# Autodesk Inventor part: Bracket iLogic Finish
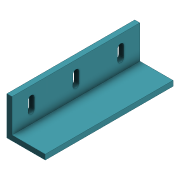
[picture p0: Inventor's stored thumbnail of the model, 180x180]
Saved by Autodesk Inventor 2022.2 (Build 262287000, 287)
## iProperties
RuleStatus: InUse
Created: 2021-08
Part Number: Bracket iLogic Finish
Material: アルミニウム 6061
Document SubType Name: Modeling
Designer: taeku
Density: 2.7 g/cm^3
Appearance: くすんだ青
Author: taeku
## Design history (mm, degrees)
sketch "スケッチ1"
  geometry: L1 (0, 0)-(30, 0); L2 (30, 0)-(30, 4); L3 (30, 4)-(4, 4); L4 (4, 4)-(4, 30); L5 (4, 30)-(0, 30); L6 (0, 30)-(0, 0)
  constraints: 12 end point, 5 perpendicular, 1 horizontal, 1 vertical
  dimensions: "幅" = 30 distance of L1.start L1.end; "d1" = 30 distance of L5.end L1.start (= 幅); "厚み" = 4 distance of L1.end L2.end
extrude "押し出し1" new body sketch "スケッチ1" taper "d4" = 0 deg
sketch "スケッチ2"
  geometry: L1 (15, 17)-(15, 9); L2 (12.5, 17)-(12.5, 9); L3 (17.5, 9)-(17.5, 17); L4 (0, 0)-(0, 26) reference; A1 r 2.5 centre (15, 17) between (17.5, 17) and (12.5, 17); A2 r 2.5 centre (15, 9) between (12.5, 9) and (17.5, 9); 3 further points
  constraints: 8 end point, 4 point on circle, 4 tangent, 2 centre point, 2 midpoint, 1 horizontal alignment, 1 parallel, 1 vertical
  dimensions: "端からの距離" = 15 distance between parallel lines of L1 L4; "d6" = 8 distance of L1.start L1.end; "d7" = 5 distance between parallel lines of L3 L2
extrude "押し出し2" cut sketch "スケッチ2" extent not by distance; stored distance "d8" = 0; taper "d9" = 0 deg
pattern_linear "矩形状パターン1" dims "d12" = 35 (derived)
node "作業平面1"
sketch "スケッチ3"
  geometry: L1 (26, -9)-(0, -9) reference; L2 (0, 0)-(0, 8) reference; L3 (0, 5.364)-(14.364, -9); 1 further point
  constraints: 2 end point, 2 point on line
  dimensions: "d13" = 45 deg angle of L3 L1
feature "リブ1" sketch "スケッチ3" dims "d14" = 1, "d15" = 3, "d16" = 0, "d17" = 0, "d18" = 1, "d19" = 1
node "作業平面2"
mirror "ミラー1"
node "ソリッド1"
